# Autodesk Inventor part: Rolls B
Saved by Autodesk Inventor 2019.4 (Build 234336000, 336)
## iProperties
Created: 2020-05
Part Number: Rolls B
Material: Generic
Document SubType Name: Modeling
Designer: Administrator
Density: 1 g/cm^3
Appearance: Default
Title: Rolls B
Author: Administrator
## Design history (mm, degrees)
feature "Body1"
feature "Body2"
feature "Body3"
feature "Body4"
feature "Body21"
feature "Body22"
feature "Body23"
feature "Body24"
feature "Body25"
feature "Body26"
feature "Body29"
feature "Body30"
feature "Body31"
body "Solid1"
body "Solid2"
body "Solid3"
body "Solid4"
body "Solid5"
body "Solid6"
body "Solid7"
body "Solid8"
body "Solid9"
body "Solid10"
body "Solid11"
body "Solid12"
body "Solid13"
